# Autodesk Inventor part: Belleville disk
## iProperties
Created: 2006-10
Part Number: Belleville disk
Document SubType Name: Modeling
Designer: John Croya
Density: 1 g/cm^3
Control State: 0
Master: False
Checked Out: False
Shininess: 64.0
Angle Display Precision: 2
Document Length Units: 11272
Document Angle Units: 11279
Document Time Units: 11290
Document Mass Units: 11286
Document Length Units Precision: 3
Document Angle Units Precision: 2
Compacted: True
Density: 0.0
Volumn: 0.0
Area: 0.0
PropertySet Name: Model Information
Author: John Croya
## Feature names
1. Revolution1
